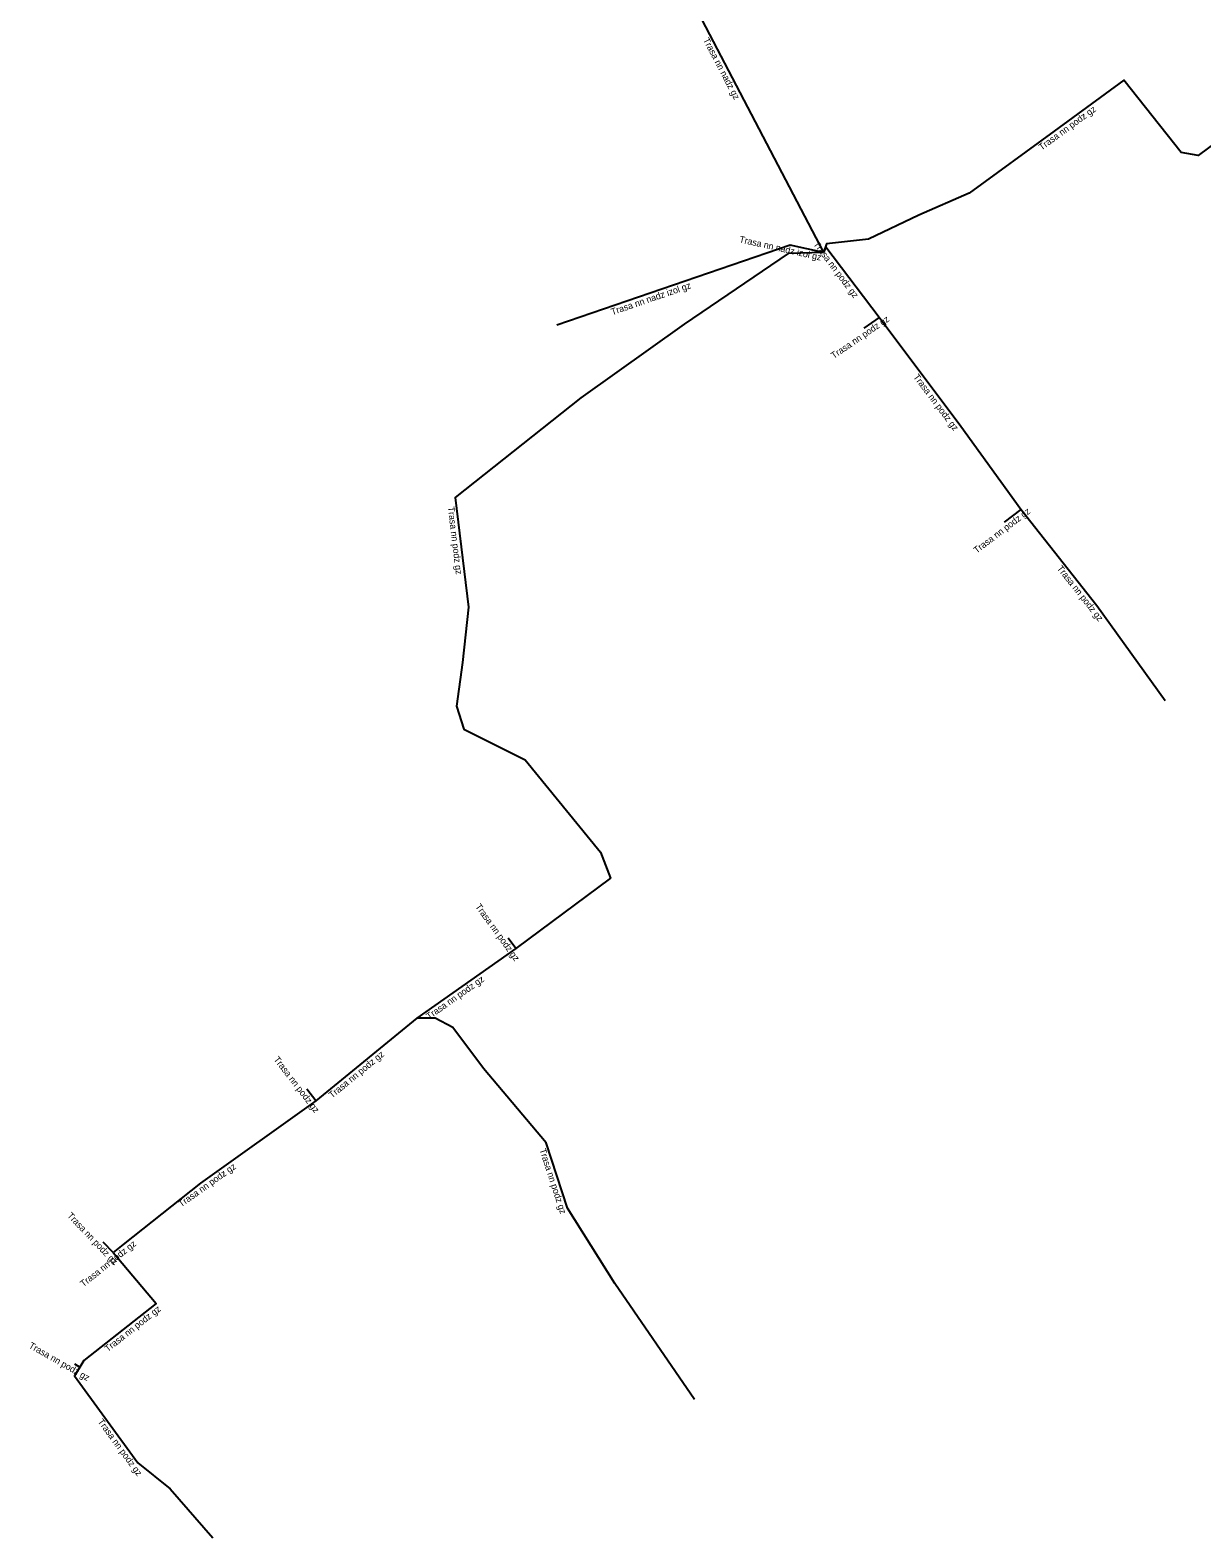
# Model space of a CAD drawing. Extents: x -468149 to -467677, y -1100197 to -1099840.
# Drawn here: x -468019.8 to -467931, y -1100185.8 to -1100071.5 of the extents above; entities that cross this region are included whole.
import ezdxf

# ---------------------------------------------------------------- set-up
doc = ezdxf.new("R2010")
doc.units = 0
doc.layers.add('Popiskový text - Ostatní atributy Trasy', color=7, linetype='Continuous')
doc.layers.add('Spojnice NN', color=7, linetype='Continuous')

msp = doc.modelspace()

# ---------------------------------------------------------------- linework, layer by layer
at = {"layer": 'Spojnice NN'}
for points in [[(-467973.2, -1100062.45), (-467959.67, -1100088.38)], [(-467923.28, -1100075.08), (-467931.27, -1100081.01), (-467932.56, -1100080.79), (-467936.92, -1100075.32), (-467942.2, -1100079.17), (-467948.64, -1100083.87), (-467952.45, -1100085.55), (-467956.25, -1100087.35), (-467959.45, -1100087.71), (-467959.67, -1100088.38)], [(-467962.19, -1100087.81), (-467979.87, -1100093.89)], [(-467959.67, -1100088.38), (-467962.19, -1100087.81)], [(-467955.46, -1100093.31), (-467959.48, -1100087.98), (-467959.67, -1100088.38)], [(-467959.67, -1100088.38), (-467962.35, -1100088.46), (-467970.22, -1100093.8), (-467978.05, -1100099.38), (-467987.57, -1100106.94), (-467986.56, -1100115.24), (-467987.01, -1100119.44), (-467987.47, -1100122.75), (-467986.93, -1100124.48), (-467982.26, -1100126.81), (-467976.56, -1100133.8), (-467975.8, -1100135.77), (-467982.99, -1100141.11)], [(-467955.46, -1100093.31), (-467956.62, -1100094.11)], [(-467944.71, -1100107.84), (-467949.25, -1100101.56), (-467955.46, -1100093.31)], [(-467944.71, -1100107.84), (-467945.99, -1100108.81)], [(-467933.77, -1100122.35), (-467938.95, -1100115.15), (-467944.71, -1100107.84)], [(-467982.99, -1100141.11), (-467983.56, -1100140.32)], [(-467982.99, -1100141.11), (-467990.48, -1100146.38)], [(-467990.48, -1100146.38), (-467998.13, -1100152.66)], [(-467969.44, -1100175.28), (-467975.48, -1100166.5), (-467979.07, -1100160.79), (-467980.68, -1100155.85), (-467985.43, -1100150.2), (-467987.75, -1100147.1), (-467989.08, -1100146.38), (-467990.48, -1100146.38)], [(-467998.13, -1100152.66), (-467998.82, -1100151.77)], [(-467998.13, -1100152.66), (-468006.87, -1100158.9), (-468012.72, -1100163.55)], [(-468013.48, -1100164.16), (-468014.24, -1100163.36)], [(-468012.72, -1100163.55), (-468013.48, -1100164.16)], [(-468013.48, -1100164.16), (-468010.24, -1100168.02), (-468015.72, -1100172.33), (-468016.02, -1100172.83)], [(-468016.43, -1100172.59), (-468016.02, -1100172.83)], [(-468016.02, -1100172.83), (-468016.42, -1100173.5), (-468011.62, -1100180.08), (-468009.16, -1100182.06), (-468005.93, -1100185.77)]]:
    msp.add_lwpolyline(points, dxfattribs=at)

# ---------------------------------------------------------------- texts
at = {"layer": 'Popiskový text - Ostatní atributy Trasy'}
for s, rotation, p in [('Trasa nn nadz gz', 297.5569, (-467968.81, -1100072.26)), ('Trasa nn podz gz', 36.0983, (-467943.14, -1100080.66)), ('Trasa nn nadz izol gz', 347.2624, (-467966.08, -1100087.59)), ('Trasa nn podz gz', 307.0244, (-467960.47, -1100087.75)), ('Trasa nn nadz izol gz', 18.9842, (-467975.67, -1100093.13)), ('Trasa nn podz gz', 34.4139, (-467958.89, -1100096.45)), ('Trasa nn podz gz', 306.9698, (-467952.89, -1100097.81)), ('Trasa nn podz gz', 276.938, (-467988.14, -1100107.66)), ('Trasa nn podz gz', 37.2041, (-467948.06, -1100111.2)), ('Trasa nn podz gz', 308.2368, (-467942.01, -1100112.32)), ('Trasa nn podz gz', 305.8654, (-467986.08, -1100137.94)), ('Trasa nn podz gz', 35.1304, (-467989.55, -1100146.52)), ('Trasa nn podz gz', 307.6106, (-468001.36, -1100149.53)), ('Trasa nn podz gz', 39.3831, (-467996.9, -1100152.49)), ('Trasa nn podz gz', 288.0514, (-467981.2, -1100156.36)), ('Trasa nn podz gz', 35.5253, (-468008.33, -1100160.74)), ('Trasa nn podz gz', 313.5911, (-468017.01, -1100161.39)), ('Trasa nn podz gz', 38.5125, (-468015.74, -1100166.79)), ('Trasa nn podz gz', 38.1849, (-468013.89, -1100171.71)), ('Trasa nn podz gz', 330.2145, (-468019.93, -1100171.34)), ('Trasa nn podz gz', 306.1101, (-468014.69, -1100176.97))]:
    msp.add_text(s, height=0.5, rotation=rotation, dxfattribs=at).set_placement(p)

doc.saveas('drawing.dxf')
